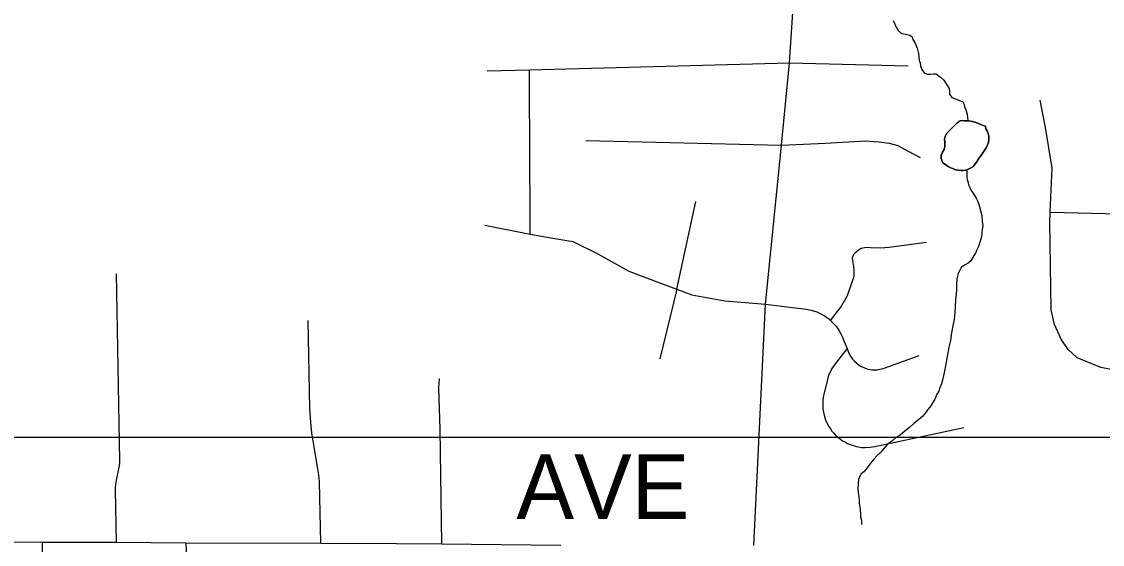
# Model space of a CAD drawing. Extents: x -59 to 82, y -3 to 49.
# Drawn here: x -52.032 to -51.082, y 46.333 to 46.792 of the extents above; entities that cross this region are included whole.
import ezdxf

# ---------------------------------------------------------------- set-up
doc = ezdxf.new("R2010")
doc.units = 0
for name, color, linetype in [('GM_X_County_Road', 7, 'Continuous'), ('GM_X_County_Road_Text', 7, 'Continuous'), ('GM_X_Minor_Lake', 7, 'Continuous'), ('GM_X_Minor_River', 7, 'Continuous'), ('GM_X_Township_Road', 7, 'Continuous'), ('SH_Data', 7, 'Continuous')]:
    doc.layers.add(name, color=color, linetype=linetype)

msp = doc.modelspace()

# ---------------------------------------------------------------- linework, layer by layer
at = {"layer": 'GM_X_County_Road'}
for p, q in [((-51.35723, 46.75606), (-51.35011, 46.86772)), ((-51.36435, 46.68374), (-51.35723, 46.75606)), ((-51.37852, 46.54397), (-51.36435, 46.68374)), ((-51.38874, 46.33189), (-51.37852, 46.54397)), ((-52.06213, 46.33518), (-52.01375, 46.33501)), ((-52.01375, 46.33501), (-51.94883, 46.33477)), ((-51.94883, 46.33477), (-51.88775, 46.33445)), ((-51.88775, 46.33445), (-51.76929, 46.33389)), ((-51.76929, 46.33389), (-51.70257, 46.33358)), ((-51.70257, 46.33358), (-51.66282, 46.33339)), ((-51.66282, 46.33339), (-51.55826, 46.33237))]:
    msp.add_line(p, q, dxfattribs=at)
at = {"layer": 'GM_X_Minor_Lake'}
for p, q in [((-51.21067, 46.70278), (-51.21934, 46.69405)), ((-51.21934, 46.69405), (-51.21067, 46.70278)), ((-51.20992, 46.70324), (-51.21067, 46.70278)), ((-51.21067, 46.70278), (-51.20992, 46.70324)), ((-51.20728, 46.70516), (-51.20992, 46.70324)), ((-51.20992, 46.70324), (-51.20728, 46.70516)), ((-51.20539, 46.70555), (-51.20728, 46.70516)), ((-51.20728, 46.70516), (-51.20539, 46.70555)), ((-51.20348, 46.70519), (-51.20539, 46.70555)), ((-51.20539, 46.70555), (-51.20348, 46.70519)), ((-51.20158, 46.7052), (-51.20348, 46.70519)), ((-51.20348, 46.70519), (-51.20158, 46.7052)), ((-51.19969, 46.70521), (-51.20158, 46.7052)), ((-51.20158, 46.7052), (-51.19969, 46.70521)), ((-51.19664, 46.70447), (-51.19969, 46.70521)), ((-51.19969, 46.70521), (-51.19664, 46.70447)), ((-51.1936, 46.70373), (-51.19664, 46.70447)), ((-51.19664, 46.70447), (-51.1936, 46.70373)), ((-51.18979, 46.70224), (-51.1936, 46.70373)), ((-51.1936, 46.70373), (-51.18979, 46.70224)), ((-51.18712, 46.70112), (-51.18979, 46.70224)), ((-51.18979, 46.70224), (-51.18712, 46.70112)), ((-51.18522, 46.70037), (-51.18712, 46.70112)), ((-51.18712, 46.70112), (-51.18522, 46.70037)), ((-51.18482, 46.69809), (-51.18522, 46.70037)), ((-51.18522, 46.70037), (-51.18482, 46.69809)), ((-51.22046, 46.69138), (-51.2212, 46.6891)), ((-51.2212, 46.6891), (-51.22046, 46.69138)), ((-51.21934, 46.69405), (-51.22046, 46.69138)), ((-51.22046, 46.69138), (-51.21934, 46.69405)), ((-51.18366, 46.6962), (-51.18482, 46.69809)), ((-51.18482, 46.69809), (-51.18366, 46.6962)), ((-51.1825, 46.69317), (-51.18366, 46.6962)), ((-51.18366, 46.6962), (-51.1825, 46.69317)), ((-51.18211, 46.69127), (-51.1825, 46.69317)), ((-51.1825, 46.69317), (-51.18211, 46.69127)), ((-51.18208, 46.68899), (-51.18211, 46.69127)), ((-51.18211, 46.69127), (-51.18208, 46.68899)), ((-51.22151, 46.67998), (-51.22301, 46.67769)), ((-51.22301, 46.67769), (-51.22151, 46.67998)), ((-51.22077, 46.68264), (-51.22151, 46.67998)), ((-51.22151, 46.67998), (-51.22077, 46.68264)), ((-51.2212, 46.6891), (-51.2208, 46.68644)), ((-51.2208, 46.68644), (-51.2212, 46.6891)), ((-51.2208, 46.68644), (-51.22078, 46.68454)), ((-51.22078, 46.68454), (-51.2208, 46.68644)), ((-51.22078, 46.68454), (-51.22077, 46.68264)), ((-51.22077, 46.68264), (-51.22078, 46.68454)), ((-51.18918, 46.6745), (-51.18456, 46.68145)), ((-51.18456, 46.68145), (-51.18918, 46.6745)), ((-51.18393, 46.68252), (-51.18458, 46.68142)), ((-51.18456, 46.68145), (-51.18393, 46.68252)), ((-51.18393, 46.68252), (-51.18244, 46.68595)), ((-51.18244, 46.68595), (-51.18393, 46.68252)), ((-51.18244, 46.68595), (-51.18208, 46.68899)), ((-51.18208, 46.68899), (-51.18244, 46.68595)), ((-51.22301, 46.67769), (-51.22412, 46.67502)), ((-51.22412, 46.67502), (-51.22301, 46.67769)), ((-51.22412, 46.67502), (-51.2241, 46.67198)), ((-51.2241, 46.67198), (-51.22412, 46.67502)), ((-51.2241, 46.67198), (-51.22255, 46.66819)), ((-51.22255, 46.66819), (-51.2241, 46.67198)), ((-51.19256, 46.66954), (-51.19069, 46.67259)), ((-51.19069, 46.67259), (-51.19256, 46.66954)), ((-51.19069, 46.67259), (-51.18918, 46.6745)), ((-51.18918, 46.6745), (-51.19069, 46.67259)), ((-51.22255, 46.66819), (-51.22026, 46.66669)), ((-51.22026, 46.66669), (-51.22255, 46.66819)), ((-51.22026, 46.66669), (-51.21835, 46.66518)), ((-51.21835, 46.66518), (-51.22026, 46.66669)), ((-51.21835, 46.66518), (-51.21606, 46.66406)), ((-51.21606, 46.66406), (-51.21835, 46.66518)), ((-51.21606, 46.66406), (-51.21339, 46.66293)), ((-51.21339, 46.66293), (-51.21606, 46.66406)), ((-51.21339, 46.66293), (-51.21111, 46.66219)), ((-51.21111, 46.66219), (-51.21339, 46.66293)), ((-51.21111, 46.66219), (-51.20883, 46.66183)), ((-51.20883, 46.66183), (-51.21111, 46.66219)), ((-51.20883, 46.66183), (-51.20654, 46.66146)), ((-51.20654, 46.66146), (-51.20883, 46.66183)), ((-51.20654, 46.66146), (-51.20465, 46.66147)), ((-51.20465, 46.66147), (-51.20654, 46.66146)), ((-51.20465, 46.66147), (-51.20275, 46.66187)), ((-51.20275, 46.66187), (-51.20465, 46.66147)), ((-51.20275, 46.66187), (-51.20086, 46.66226)), ((-51.20086, 46.66226), (-51.20275, 46.66187)), ((-51.20086, 46.66226), (-51.19859, 46.66342)), ((-51.19859, 46.66342), (-51.20086, 46.66226)), ((-51.19859, 46.66342), (-51.19632, 46.66457)), ((-51.19632, 46.66457), (-51.19859, 46.66342)), ((-51.19632, 46.66457), (-51.19444, 46.66686)), ((-51.19444, 46.66686), (-51.19632, 46.66457)), ((-51.19444, 46.66686), (-51.19256, 46.66954)), ((-51.19256, 46.66954), (-51.19444, 46.66686))]:
    msp.add_line(p, q, dxfattribs=at)
at = {"layer": 'GM_X_Minor_River'}
for p, q in [((-51.2661, 46.79329), (-51.26455, 46.7895)), ((-51.26455, 46.7895), (-51.26339, 46.78685)), ((-51.26339, 46.78685), (-51.26185, 46.78458)), ((-51.26185, 46.78458), (-51.25879, 46.78194)), ((-51.25879, 46.78194), (-51.25537, 46.78121)), ((-51.25537, 46.78121), (-51.25156, 46.78047)), ((-51.25156, 46.78047), (-51.24965, 46.77897)), ((-51.24965, 46.77897), (-51.24887, 46.77669)), ((-51.24887, 46.77669), (-51.24695, 46.77328)), ((-51.24695, 46.77328), (-51.24501, 46.76912)), ((-51.24501, 46.76912), (-51.24383, 46.76419)), ((-51.24383, 46.76419), (-51.24341, 46.75811)), ((-51.24341, 46.75811), (-51.24263, 46.75621)), ((-51.24263, 46.75621), (-51.24223, 46.75356)), ((-51.24223, 46.75356), (-51.24106, 46.75014)), ((-51.24106, 46.75014), (-51.23876, 46.74712)), ((-51.23876, 46.74712), (-51.23609, 46.746)), ((-51.23305, 46.74602), (-51.23078, 46.74642)), ((-51.23078, 46.74642), (-51.2285, 46.74643)), ((-51.2285, 46.74643), (-51.22468, 46.74342)), ((-51.23609, 46.746), (-51.23305, 46.74602)), ((-51.22468, 46.74342), (-51.22162, 46.74078)), ((-51.22162, 46.74078), (-51.21701, 46.73359)), ((-51.21701, 46.73359), (-51.2166, 46.73056)), ((-51.2166, 46.73056), (-51.21659, 46.72865)), ((-51.21659, 46.72865), (-51.21466, 46.72563)), ((-51.21466, 46.72563), (-51.21085, 46.72413)), ((-51.21085, 46.72413), (-51.20704, 46.72264)), ((-51.20704, 46.72264), (-51.20514, 46.72189)), ((-51.20514, 46.72189), (-51.20398, 46.71962)), ((-51.20398, 46.71962), (-51.20358, 46.71734)), ((-51.20358, 46.71734), (-51.20242, 46.71469)), ((-51.20242, 46.71469), (-51.20125, 46.7109)), ((-51.20125, 46.7109), (-51.20052, 46.7052)), ((-51.20148, 46.66165), (-51.20156, 46.6558)), ((-51.20156, 46.6558), (-51.20116, 46.65352)), ((-51.20116, 46.65352), (-51.20038, 46.65086)), ((-51.20038, 46.65086), (-51.19999, 46.64897)), ((-51.19999, 46.64897), (-51.19883, 46.64669)), ((-51.19883, 46.64669), (-51.19767, 46.64404)), ((-51.19767, 46.64404), (-51.19575, 46.64102)), ((-51.19575, 46.64102), (-51.19344, 46.63723)), ((-51.19344, 46.63723), (-51.19189, 46.6342)), ((-51.19189, 46.6342), (-51.19073, 46.63079)), ((-51.19073, 46.63079), (-51.18955, 46.62624)), ((-51.18955, 46.62624), (-51.18838, 46.62206)), ((-51.18838, 46.62206), (-51.18796, 46.61675)), ((-51.18796, 46.61675), (-51.18754, 46.61295)), ((-51.18825, 46.6061), (-51.18897, 46.60192)), ((-51.1879, 46.60953), (-51.18825, 46.6061)), ((-51.18754, 46.61295), (-51.1879, 46.60953)), ((-51.19119, 46.59468), (-51.19269, 46.59163)), ((-51.19008, 46.59849), (-51.19119, 46.59468)), ((-51.18897, 46.60192), (-51.19008, 46.59849)), ((-51.19493, 46.58706), (-51.19643, 46.58439)), ((-51.1938, 46.58897), (-51.19493, 46.58706)), ((-51.19269, 46.59163), (-51.1938, 46.58897)), ((-51.20661, 46.57634), (-51.20923, 46.571)), ((-51.20359, 46.57826), (-51.20661, 46.57634)), ((-51.20019, 46.58018), (-51.20359, 46.57826)), ((-51.1983, 46.58171), (-51.20019, 46.58018)), ((-51.19643, 46.58439), (-51.1983, 46.58171)), ((-51.21033, 46.56643), (-51.21067, 46.56149)), ((-51.20923, 46.571), (-51.21033, 46.56643)), ((-51.21063, 46.55731), (-51.21098, 46.55274)), ((-51.21067, 46.56149), (-51.21063, 46.55731)), ((-51.21132, 46.5478), (-51.21165, 46.5421)), ((-51.21098, 46.55274), (-51.21132, 46.5478)), ((-51.21165, 46.5421), (-51.21198, 46.5364)), ((-51.2127, 46.53069), (-51.21379, 46.52498)), ((-51.21198, 46.5364), (-51.2127, 46.53069)), ((-51.21488, 46.5189), (-51.21596, 46.51205)), ((-51.21379, 46.52498), (-51.21488, 46.5189)), ((-51.21596, 46.51205), (-51.21744, 46.50634)), ((-51.21744, 46.50634), (-51.22034, 46.48998)), ((-51.22034, 46.48998), (-51.22143, 46.48389)), ((-51.22143, 46.48389), (-51.22253, 46.47856)), ((-51.22363, 46.47399), (-51.22512, 46.47056)), ((-51.22253, 46.47856), (-51.22363, 46.47399)), ((-51.22773, 46.46484), (-51.2296, 46.46065)), ((-51.22623, 46.46751), (-51.22773, 46.46484)), ((-51.22512, 46.47056), (-51.22623, 46.46751)), ((-51.23409, 46.4534), (-51.23597, 46.4511)), ((-51.23222, 46.45607), (-51.23409, 46.4534)), ((-51.2296, 46.46065), (-51.23222, 46.45607)), ((-51.24388, 46.44231), (-51.24803, 46.43924)), ((-51.24048, 46.44537), (-51.24388, 46.44231)), ((-51.23785, 46.44843), (-51.24048, 46.44537)), ((-51.23597, 46.4511), (-51.23785, 46.44843)), ((-51.2518, 46.43579), (-51.25595, 46.43234)), ((-51.24803, 46.43924), (-51.2518, 46.43579)), ((-51.26727, 46.42352), (-51.27142, 46.42084)), ((-51.26426, 46.42659), (-51.26727, 46.42352)), ((-51.2601, 46.4289), (-51.26426, 46.42659)), ((-51.25595, 46.43234), (-51.2601, 46.4289)), ((-51.27706, 46.41396), (-51.28046, 46.41089)), ((-51.27405, 46.4174), (-51.27706, 46.41396)), ((-51.27142, 46.42084), (-51.27405, 46.4174)), ((-51.2861, 46.40439), (-51.2891, 46.40019)), ((-51.28309, 46.40783), (-51.2861, 46.40439)), ((-51.28046, 46.41089), (-51.28309, 46.40783)), ((-51.29438, 46.39483), (-51.2955, 46.39292)), ((-51.29211, 46.39675), (-51.29438, 46.39483)), ((-51.2891, 46.40019), (-51.29211, 46.39675)), ((-51.29696, 46.38607), (-51.29731, 46.38227)), ((-51.29661, 46.38988), (-51.29696, 46.38607)), ((-51.2955, 46.39292), (-51.29661, 46.38988)), ((-51.29731, 46.38227), (-51.2969, 46.37847)), ((-51.2969, 46.37847), (-51.29649, 46.37506)), ((-51.29649, 46.37506), (-51.29609, 46.37164)), ((-51.29609, 46.37164), (-51.29607, 46.36898)), ((-51.29607, 46.36898), (-51.29566, 46.36594)), ((-51.29566, 46.36594), (-51.29526, 46.36291)), ((-51.29526, 46.36291), (-51.29485, 46.35987)), ((-51.29485, 46.35987), (-51.29483, 46.35721)), ((-51.29483, 46.35721), (-51.29443, 46.35531)), ((-51.29443, 46.35531), (-51.29404, 46.35303)), ((-51.29404, 46.35303), (-51.29402, 46.35113)), ((-51.29402, 46.35113), (-51.29401, 46.35037))]:
    msp.add_line(p, q, dxfattribs=at)
at = {"layer": 'GM_X_Township_Road'}
for p, q in [((-51.58583, 46.75002), (-51.35723, 46.75606)), ((-51.35723, 46.75606), (-51.25315, 46.75334)), ((-51.62297, 46.74904), (-51.58583, 46.75002)), ((-51.58546, 46.6634), (-51.58583, 46.75002)), ((-51.13224, 46.6992), (-51.13708, 46.72327)), ((-51.12654, 46.66347), (-51.13224, 46.6992)), ((-51.53632, 46.68779), (-51.36435, 46.68374)), ((-51.36435, 46.68374), (-51.32565, 46.68546)), ((-51.32565, 46.68546), (-51.29046, 46.68751)), ((-51.29046, 46.68751), (-51.27873, 46.68681)), ((-51.27873, 46.68681), (-51.26977, 46.68543)), ((-51.26977, 46.68543), (-51.26218, 46.68335)), ((-51.26218, 46.68335), (-51.2532, 46.67844)), ((-51.2532, 46.67844), (-51.24258, 46.67278)), ((-51.58534, 46.63453), (-51.58546, 46.6634)), ((-51.12831, 46.62499), (-51.12654, 46.66347)), ((-51.58521, 46.60566), (-51.58534, 46.63453)), ((-51.45626, 46.5571), (-51.43973, 46.63433)), ((-51.1287, 46.61631), (-51.12831, 46.62499)), ((-51.12831, 46.62499), (-51.06723, 46.62341)), ((-51.62492, 46.61333), (-51.58521, 46.60566)), ((-51.12731, 46.53912), (-51.1287, 46.61631)), ((-51.58521, 46.60566), (-51.56531, 46.60194)), ((-51.56531, 46.60194), (-51.5478, 46.59902)), ((-51.5478, 46.59902), (-51.52629, 46.58861)), ((-51.26964, 46.59403), (-51.23698, 46.5986)), ((-51.52629, 46.58861), (-51.49858, 46.57307)), ((-51.30197, 46.58422), (-51.30176, 46.58629)), ((-51.30176, 46.58629), (-51.30053, 46.58814)), ((-51.30053, 46.58814), (-51.29887, 46.59)), ((-51.29887, 46.59), (-51.2967, 46.59186)), ((-51.2967, 46.59186), (-51.29432, 46.5933)), ((-51.29432, 46.5933), (-51.29143, 46.59382)), ((-51.29143, 46.59382), (-51.28885, 46.59402)), ((-51.28885, 46.59402), (-51.28617, 46.59382)), ((-51.28617, 46.59382), (-51.27739, 46.5935)), ((-51.27739, 46.5935), (-51.26964, 46.59403)), ((-51.30135, 46.5805), (-51.30197, 46.58422)), ((-51.30094, 46.57709), (-51.30135, 46.5805)), ((-51.30053, 46.57369), (-51.30094, 46.57709)), ((-51.94571, 46.40665), (-51.94871, 46.57068)), ((-51.49858, 46.57307), (-51.46986, 46.56212)), ((-51.30648, 46.55168), (-51.30053, 46.56852)), ((-51.30053, 46.57224), (-51.30053, 46.57369)), ((-51.30053, 46.56852), (-51.30053, 46.57224)), ((-51.45626, 46.5571), (-51.47138, 46.49602)), ((-51.46986, 46.56212), (-51.45626, 46.5571)), ((-51.45626, 46.5571), (-51.44306, 46.55224)), ((-51.44306, 46.55224), (-51.41412, 46.54698)), ((-51.41412, 46.54698), (-51.37852, 46.54397)), ((-51.31224, 46.54131), (-51.30648, 46.55168)), ((-51.37852, 46.54397), (-51.34278, 46.53955)), ((-51.34278, 46.53955), (-51.33815, 46.53868)), ((-51.33815, 46.53868), (-51.3334, 46.53723)), ((-51.32128, 46.52982), (-51.31224, 46.54131)), ((-51.12446, 46.52625), (-51.12731, 46.53912)), ((-51.77871, 46.45242), (-51.78023, 46.52972)), ((-51.3334, 46.53723), (-51.32973, 46.53547)), ((-51.32973, 46.53547), (-51.32669, 46.53382)), ((-51.32669, 46.53382), (-51.32313, 46.5314)), ((-51.32313, 46.5314), (-51.32128, 46.52982)), ((-51.32128, 46.52982), (-51.31652, 46.52488)), ((-51.31652, 46.52488), (-51.31404, 46.52126)), ((-51.31404, 46.52126), (-51.31218, 46.51805)), ((-51.11874, 46.51338), (-51.12446, 46.52625)), ((-51.31218, 46.51805), (-51.31074, 46.51495)), ((-51.31074, 46.51495), (-51.30925, 46.51113)), ((-51.30925, 46.51113), (-51.30675, 46.50516)), ((-51.11232, 46.50409), (-51.11874, 46.51338)), ((-51.30675, 46.50516), (-51.31731, 46.49155)), ((-51.30675, 46.50516), (-51.30569, 46.50241)), ((-51.30569, 46.50241), (-51.3043, 46.49931)), ((-51.3043, 46.49931), (-51.30187, 46.49574)), ((-51.10446, 46.49693), (-51.11232, 46.50409)), ((-51.31731, 46.49155), (-51.31869, 46.48953)), ((-51.30187, 46.49574), (-51.30017, 46.49383)), ((-51.30017, 46.49383), (-51.2978, 46.49181)), ((-51.2978, 46.49181), (-51.29501, 46.48959)), ((-51.27416, 46.48782), (-51.24352, 46.49895)), ((-51.08374, 46.48835), (-51.10446, 46.49693)), ((-51.32293, 46.48167), (-51.32438, 46.47675)), ((-51.32158, 46.48441), (-51.32293, 46.48167)), ((-51.32019, 46.48756), (-51.32158, 46.48441)), ((-51.31869, 46.48953), (-51.32019, 46.48756)), ((-51.29501, 46.48959), (-51.2915, 46.48794)), ((-51.2915, 46.48794), (-51.2884, 46.48685)), ((-51.2884, 46.48685), (-51.28494, 46.48638)), ((-51.28494, 46.48638), (-51.28024, 46.48633)), ((-51.28024, 46.48633), (-51.27416, 46.48782)), ((-51.05656, 46.48318), (-51.08374, 46.48835)), ((-51.66535, 46.47056), (-51.66483, 46.47883)), ((-51.32438, 46.47675), (-51.3272, 46.46457)), ((-51.66433, 46.43418), (-51.66535, 46.47056)), ((-51.32764, 46.46221), (-51.328, 46.45973)), ((-51.3272, 46.46457), (-51.32764, 46.46221)), ((-51.7781, 46.4404), (-51.77871, 46.45242)), ((-51.328, 46.45973), (-51.32816, 46.45746)), ((-51.32816, 46.45746), (-51.32811, 46.45451)), ((-51.32811, 46.45451), (-51.328, 46.45209)), ((-51.328, 46.45209), (-51.32754, 46.44904)), ((-51.32754, 46.44904), (-51.32697, 46.44635)), ((-51.32697, 46.44635), (-51.326, 46.4432)), ((-51.326, 46.4432), (-51.32475, 46.44021)), ((-51.77701, 46.43053), (-51.7781, 46.4404)), ((-51.66282, 46.33339), (-51.66433, 46.43418)), ((-51.32475, 46.44021), (-51.3228, 46.43654)), ((-51.3228, 46.43654), (-51.32135, 46.43437)), ((-51.32135, 46.43437), (-51.32011, 46.43256)), ((-51.2824, 46.41895), (-51.20415, 46.43552)), ((-51.77597, 46.42399), (-51.77701, 46.43053)), ((-51.77082, 46.39395), (-51.77597, 46.42399)), ((-51.32011, 46.43256), (-51.31836, 46.43055)), ((-51.31836, 46.43055), (-51.31655, 46.42869)), ((-51.31655, 46.42869), (-51.31475, 46.42709)), ((-51.31475, 46.42709), (-51.31284, 46.42559)), ((-51.31284, 46.42559), (-51.31062, 46.42403)), ((-51.31062, 46.42403), (-51.30814, 46.42269)), ((-51.30814, 46.42269), (-51.30633, 46.42171)), ((-51.30633, 46.42171), (-51.30302, 46.42037)), ((-51.30302, 46.42037), (-51.29881, 46.41909)), ((-51.29881, 46.41909), (-51.29657, 46.4186)), ((-51.29657, 46.4186), (-51.29405, 46.41819)), ((-51.29405, 46.41819), (-51.29085, 46.41803)), ((-51.29085, 46.41803), (-51.28645, 46.41829)), ((-51.28645, 46.41829), (-51.2824, 46.41895)), ((-51.9461, 46.40204), (-51.94581, 46.40467)), ((-51.94581, 46.40467), (-51.94571, 46.40665)), ((-51.9488, 46.38945), (-51.94657, 46.39943)), ((-51.94657, 46.39943), (-51.9461, 46.40204)), ((-51.94947, 46.38519), (-51.94942, 46.38585)), ((-51.94942, 46.38585), (-51.9488, 46.38945)), ((-51.77026, 46.38822), (-51.77082, 46.39395)), ((-51.76929, 46.33389), (-51.77026, 46.38822)), ((-51.94966, 46.3832), (-51.94947, 46.38519)), ((-51.94966, 46.38056), (-51.94966, 46.3832)), ((-51.94883, 46.33477), (-51.94966, 46.38056)), ((-52.01158, 46.20964), (-52.01375, 46.33501)), ((-51.88775, 46.33445), (-51.8853, 46.25905))]:
    msp.add_line(p, q, dxfattribs=at)
at = {"layer": 'SH_Data'}
msp.add_lwpolyline([(-52.16577, 45.73353), (-50.40823, 45.73353), (-50.40823, 46.42698), (-52.16577, 46.42698)], close=True, dxfattribs=at)
msp.add_lwpolyline([(-52.16577, 45.73353), (-50.40823, 45.73353), (-50.40823, 46.42698), (-52.16577, 46.42698)], close=True, dxfattribs=at)

# ---------------------------------------------------------------- texts
at = {"layer": 'GM_X_County_Road_Text'}
msp.add_text('AVE', height=0.056818, rotation=0.00001, dxfattribs=at).set_placement((-51.59734, 46.35526))

doc.saveas('drawing.dxf')
